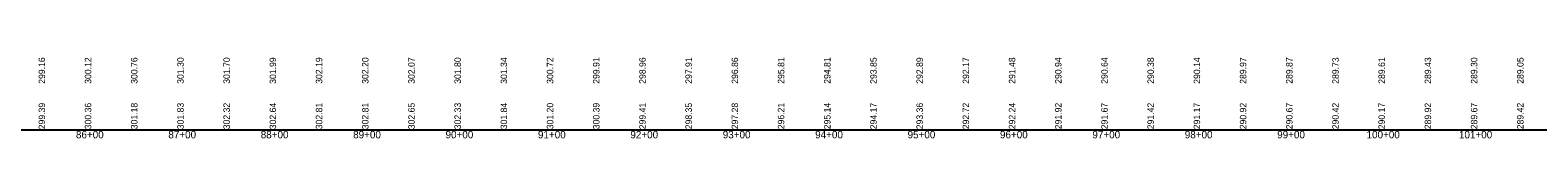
# Model space of a CAD drawing. Extents: x 1876258 to 1926563, y 729739 to 834437.
# Drawn here: x 1886896 to 1888528, y 827954 to 828041 of the extents above; entities that cross this region are included whole.
import ezdxf

# ---------------------------------------------------------------- set-up
doc = ezdxf.new("R2010")
doc.units = 0
for name, color, linetype in [('RD_EX_RailRoad', 7, 'Continuous'), ('RD_PD_ALT3_CL', 7, 'Continuous'), ('RD_PD_Final_Cl', 7, 'Continuous')]:
    doc.layers.add(name, color=color, linetype=linetype)

msp = doc.modelspace()

# ---------------------------------------------------------------- linework, layer by layer
at = {"layer": 'RD_PD_Final_Cl'}
msp.add_line((1878363.1, 827962.8), (1926563.1, 827962.8), dxfattribs=at)

# ---------------------------------------------------------------- texts
at = {"layer": 'RD_EX_RailRoad'}
for s, p in [('299.16', (1886912.1, 828012.8)), ('300.12', (1886962.1, 828012.8)), ('300.76', (1887012.1, 828012.8)), ('301.30', (1887062.1, 828012.8)), ('301.70', (1887112.1, 828012.8)), ('301.99', (1887162.1, 828012.8)), ('302.19', (1887212.1, 828012.8)), ('302.20', (1887262.1, 828012.8)), ('302.07', (1887312.1, 828012.8)), ('301.80', (1887362.1, 828012.8)), ('301.34', (1887412.1, 828012.8)), ('300.72', (1887462.1, 828012.8)), ('299.91', (1887512.1, 828012.8)), ('298.96', (1887562.1, 828012.8)), ('297.91', (1887612.1, 828012.8)), ('296.86', (1887662.1, 828012.8)), ('295.81', (1887712.1, 828012.8)), ('294.81', (1887762.1, 828012.8)), ('293.85', (1887812.1, 828012.8)), ('292.89', (1887862.1, 828012.8)), ('292.17', (1887912.1, 828012.8)), ('291.48', (1887962.1, 828012.8)), ('290.94', (1888012.1, 828012.8)), ('290.64', (1888062.1, 828012.8)), ('290.38', (1888112.1, 828012.8)), ('290.14', (1888162.1, 828012.8)), ('289.97', (1888212.1, 828012.8)), ('289.87', (1888262.1, 828012.8)), ('289.73', (1888312.1, 828012.8)), ('289.61', (1888362.1, 828012.8)), ('289.43', (1888412.1, 828012.8)), ('289.30', (1888462.1, 828012.8)), ('289.05', (1888512.1, 828012.8)), ('299.39', (1886912.1, 827963.6)), ('300.36', (1886962.1, 827963.6)), ('301.18', (1887012.1, 827963.6)), ('301.83', (1887062.1, 827963.6)), ('302.32', (1887112.1, 827963.6)), ('302.64', (1887162.1, 827963.6)), ('302.81', (1887212.1, 827963.6)), ('302.81', (1887262.1, 827963.6)), ('302.65', (1887312.1, 827963.6)), ('302.33', (1887362.1, 827963.6)), ('301.84', (1887412.1, 827963.6)), ('301.20', (1887462.1, 827963.6)), ('300.39', (1887512.1, 827963.6)), ('299.41', (1887562.1, 827963.6)), ('298.35', (1887612.1, 827963.6)), ('297.28', (1887662.1, 827963.6)), ('296.21', (1887712.1, 827963.6)), ('295.14', (1887762.1, 827963.6)), ('294.17', (1887812.1, 827963.6)), ('293.36', (1887862.1, 827963.6)), ('292.72', (1887912.1, 827963.6)), ('292.24', (1887962.1, 827963.6)), ('291.92', (1888012.1, 827963.6)), ('291.67', (1888062.1, 827963.6)), ('291.42', (1888112.1, 827963.6)), ('291.17', (1888162.1, 827963.6)), ('290.92', (1888212.1, 827963.6)), ('290.67', (1888262.1, 827963.6)), ('290.42', (1888312.1, 827963.6)), ('290.17', (1888362.1, 827963.6)), ('289.92', (1888412.1, 827963.6)), ('289.67', (1888462.1, 827963.6)), ('289.42', (1888512.1, 827963.6))]:
    msp.add_text(s, height=7, rotation=90, dxfattribs=at).set_placement(p)
at = {"layer": 'RD_PD_ALT3_CL'}
for s, p in [('86+00', (1886945.5, 827953.8)), ('87+00', (1887045.5, 827953.8)), ('88+00', (1887145.5, 827953.8)), ('89+00', (1887245.5, 827953.8)), ('90+00', (1887345.5, 827953.8)), ('91+00', (1887445.5, 827953.8)), ('92+00', (1887545.5, 827953.8)), ('93+00', (1887645.5, 827953.8)), ('94+00', (1887745.5, 827953.8)), ('95+00', (1887845.5, 827953.8)), ('96+00', (1887945.5, 827953.8)), ('97+00', (1888045.5, 827953.8)), ('98+00', (1888145.5, 827953.8)), ('99+00', (1888245.5, 827953.8)), ('100+00', (1888342.2, 827953.8)), ('101+00', (1888442.2, 827953.8))]:
    msp.add_text(s, height=8, dxfattribs=at).set_placement(p)

doc.saveas('drawing.dxf')
